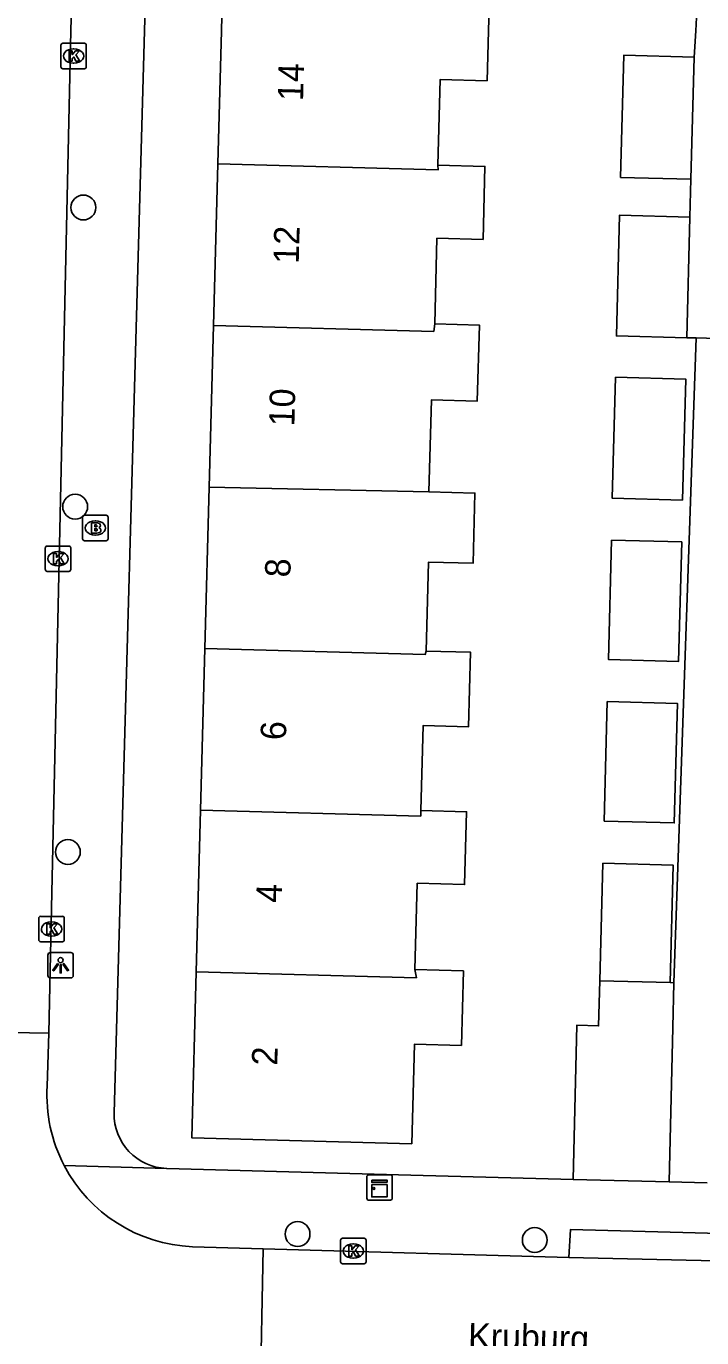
# Model space of a CAD drawing. Extents: x 162082 to 163393, y 388091 to 388632.
# Drawn here: x 162394.2 to 162420.8, y 388198.6 to 388250.2 of the extents above; entities that cross this region are included whole.
import ezdxf

# ---------------------------------------------------------------- set-up
doc = ezdxf.new("R2010")
doc.units = 0
for name, color, linetype in [('IMGEO_Boom', 7, 'Continuous'), ('IMGEO_Brandkraan', 7, 'Continuous'), ('IMGEO_Kast', 7, 'Continuous'), ('IMGEO_Kolk', 7, 'Continuous'), ('IMGEO_Lichtpunt', 7, 'Continuous'), ('IMGEO_Muur', 7, 'Continuous'), ('IMGEO_Openbare_ruimte_label', 7, 'Continuous'), ('IMGEO_Pand', 7, 'Continuous'), ('IMGEO_Pand_nummerreeks', 7, 'Continuous'), ('IMGEO_Rijbaan_lokaal_open', 7, 'Continuous'), ('IMGEO_Voetpad_open', 7, 'Continuous')]:
    doc.layers.add(name, color=color, linetype=linetype)

msp = doc.modelspace()

# ---------------------------------------------------------------- linework, layer by layer
at = {"layer": 'IMGEO_Boom'}
for centre in [(162396.454, 388243.049), (162396.132, 388231.285), (162395.845, 388217.705), (162404.875, 388202.681), (162414.202, 388202.447)]:
    msp.add_circle(centre, 0.489, dxfattribs=at)
at = {"layer": 'IMGEO_Brandkraan'}
for p, q in [((162396.426, 388230.021), (162396.426, 388230.873)), ((162396.501, 388230.947), (162397.353, 388230.947)), ((162396.914, 388230.727), (162396.939, 388230.727)), ((162397.427, 388230.873), (162397.427, 388230.021)), ((162396.937, 388230.167), (162396.912, 388230.167)), ((162397.353, 388229.947), (162396.501, 388229.947))]:
    msp.add_line(p, q, dxfattribs=at)
for points in [[(162396.426, 388230.021), (162396.426, 388230.873)], [(162396.501, 388230.947), (162397.353, 388230.947)], [(162397.427, 388230.873), (162397.427, 388230.021)], [(162396.774, 388230.647), (162396.774, 388230.247), (162396.987, 388230.247)], [(162397.005, 388230.647), (162396.774, 388230.647)], [(162396.953, 388230.566), (162396.899, 388230.566), (162396.899, 388230.49)], [(162396.899, 388230.49), (162396.952, 388230.49)], [(162396.961, 388230.414), (162396.899, 388230.414), (162396.899, 388230.333)], [(162396.899, 388230.333), (162396.961, 388230.333)], [(162397.353, 388229.947), (162396.501, 388229.947)]]:
    msp.add_lwpolyline(points, dxfattribs=at)
for centre, radius, start, end in [((162396.503, 388230.871), 0.0765, 91.552, 178.448), ((162396.503, 388230.871), 0.0765, 91.552, 178.448), ((162397.351, 388230.871), 0.0765, 1.552, 88.448), ((162397.351, 388230.871), 0.0765, 1.552, 88.448), ((162396.954, 388230.528), 0.0379, 267.8285, 90.9355), ((162396.962, 388230.373), 0.0404, 269.8759, 90.5077), ((162396.993, 388230.498), 0.251, 268.6676, 293.5347), ((162397.009, 388230.502), 0.145, 59.4692, 91.5367), ((162397.034, 388230.549), 0.0922, 285.5137, 58.1501), ((162397.039, 388230.357), 0.105, 301.3115, 78.989), ((162396.503, 388230.023), 0.0765, 181.552, 268.448), ((162396.503, 388230.023), 0.0765, 181.552, 268.448), ((162397.351, 388230.023), 0.0765, 271.552, 358.448), ((162397.351, 388230.023), 0.0765, 271.552, 358.448)]:
    msp.add_arc(centre, radius, start, end, dxfattribs=at)
for centre, major_axis, ratio, start_param, end_param in [((162396.913, 388230.447), (-0.387, 0.002), 0.722429, 4.712389, 7.853982), ((162396.938, 388230.447), (-0.39, 0.002), 0.717154, 1.570796, 4.712389)]:
    msp.add_ellipse(centre, major_axis=major_axis, ratio=ratio, start_param=start_param, end_param=end_param, dxfattribs=at)
at = {"layer": 'IMGEO_Kast'}
for p, q in [((162407.599, 388204.088), (162407.599, 388204.929)), ((162407.599, 388204.929), (162407.599, 388204.088)), ((162407.674, 388205.013), (162408.515, 388205.013)), ((162408.515, 388205.013), (162407.674, 388205.013)), ((162408.599, 388204.938), (162408.599, 388204.097)), ((162408.599, 388204.097), (162408.599, 388204.938)), ((162408.524, 388204.013), (162407.683, 388204.013)), ((162407.683, 388204.013), (162408.524, 388204.013))]:
    msp.add_line(p, q, dxfattribs=at)
for points in [[(162407.794, 388204.803), (162408.394, 388204.803), (162408.394, 388204.718), (162407.794, 388204.718), (162407.794, 388204.803)], [(162407.794, 388204.628), (162408.394, 388204.628), (162408.394, 388204.139), (162407.794, 388204.139), (162407.794, 388204.628)]]:
    msp.add_lwpolyline(points, dxfattribs=at)
msp.add_circle((162407.878, 388204.477), 0.0377, dxfattribs=at)
for centre, start, end in [((162407.677, 388204.935), 92.4484, 184.2845), ((162407.677, 388204.935), 92.4484, 184.2845), ((162408.521, 388204.935), 2.4484, 94.2845), ((162408.521, 388204.935), 2.4484, 94.2845), ((162407.677, 388204.091), 182.4484, 274.2845), ((162407.677, 388204.091), 182.4484, 274.2845), ((162408.521, 388204.091), 272.4484, 4.2845), ((162408.521, 388204.091), 272.4484, 4.2845)]:
    msp.add_arc(centre, 0.0779, start, end, dxfattribs=at)
at = {"layer": 'IMGEO_Kolk'}
for p, q in [((162395.569, 388248.579), (162395.569, 388249.431)), ((162395.644, 388249.505), (162396.496, 388249.505)), ((162396.057, 388249.285), (162396.082, 388249.285)), ((162396.57, 388249.431), (162396.57, 388248.579)), ((162396.08, 388248.725), (162396.055, 388248.725)), ((162396.496, 388248.505), (162395.644, 388248.505)), ((162394.959, 388228.811), (162394.959, 388229.663)), ((162395.034, 388229.737), (162395.886, 388229.737)), ((162395.96, 388229.663), (162395.96, 388228.811)), ((162395.447, 388229.517), (162395.472, 388229.517)), ((162395.886, 388228.737), (162395.034, 388228.737)), ((162395.47, 388228.957), (162395.445, 388228.957)), ((162394.702, 388214.249), (162394.702, 388215.101)), ((162394.777, 388215.175), (162395.629, 388215.175)), ((162395.19, 388214.955), (162395.215, 388214.955)), ((162395.703, 388215.101), (162395.703, 388214.249)), ((162395.629, 388214.175), (162394.777, 388214.175)), ((162395.213, 388214.395), (162395.188, 388214.395)), ((162406.566, 388201.589), (162406.566, 388202.441)), ((162406.641, 388202.515), (162407.493, 388202.515)), ((162407.054, 388202.295), (162407.079, 388202.295)), ((162407.567, 388202.441), (162407.567, 388201.589)), ((162407.493, 388201.515), (162406.641, 388201.515)), ((162407.077, 388201.735), (162407.052, 388201.735))]:
    msp.add_line(p, q, dxfattribs=at)
for points in [[(162395.569, 388248.579), (162395.569, 388249.431)], [(162395.644, 388249.505), (162396.496, 388249.505)], [(162396.57, 388249.431), (162396.57, 388248.579)], [(162395.89, 388249.205), (162396.013, 388249.205), (162396.013, 388249.054), (162396.143, 388249.205), (162396.307, 388249.205), (162396.161, 388249.054), (162396.314, 388248.805), (162396.162, 388248.805), (162396.077, 388248.969), (162396.013, 388248.902), (162396.013, 388248.805), (162395.89, 388248.805), (162395.89, 388249.205)], [(162396.496, 388248.505), (162395.644, 388248.505)], [(162394.959, 388228.811), (162394.959, 388229.663)], [(162395.034, 388229.737), (162395.886, 388229.737)], [(162395.96, 388229.663), (162395.96, 388228.811)], [(162395.28, 388229.437), (162395.403, 388229.437), (162395.403, 388229.286), (162395.533, 388229.437), (162395.697, 388229.437), (162395.551, 388229.286), (162395.704, 388229.037), (162395.552, 388229.037), (162395.467, 388229.201), (162395.403, 388229.134), (162395.403, 388229.037), (162395.28, 388229.037), (162395.28, 388229.437)], [(162395.886, 388228.737), (162395.034, 388228.737)], [(162394.702, 388214.249), (162394.702, 388215.101)], [(162394.777, 388215.175), (162395.629, 388215.175)], [(162395.023, 388214.875), (162395.146, 388214.875), (162395.146, 388214.724), (162395.276, 388214.875), (162395.44, 388214.875), (162395.294, 388214.724), (162395.447, 388214.475), (162395.295, 388214.475), (162395.21, 388214.639), (162395.146, 388214.572), (162395.146, 388214.475), (162395.023, 388214.475), (162395.023, 388214.875)], [(162395.703, 388215.101), (162395.703, 388214.249)], [(162395.629, 388214.175), (162394.777, 388214.175)], [(162406.566, 388201.589), (162406.566, 388202.441)], [(162406.641, 388202.515), (162407.493, 388202.515)], [(162407.567, 388202.441), (162407.567, 388201.589)], [(162406.887, 388202.215), (162407.01, 388202.215), (162407.01, 388202.064), (162407.14, 388202.215), (162407.304, 388202.215), (162407.158, 388202.064), (162407.311, 388201.815), (162407.159, 388201.815), (162407.074, 388201.979), (162407.01, 388201.912), (162407.01, 388201.815), (162406.887, 388201.815), (162406.887, 388202.215)], [(162407.493, 388201.515), (162406.641, 388201.515)]]:
    msp.add_lwpolyline(points, dxfattribs=at)
for centre, start, end in [((162395.646, 388249.429), 91.552, 178.448), ((162395.646, 388249.429), 91.552, 178.448), ((162396.494, 388249.429), 1.552, 88.448), ((162396.494, 388249.429), 1.552, 88.448), ((162395.646, 388248.581), 181.552, 268.448), ((162395.646, 388248.581), 181.552, 268.448), ((162396.494, 388248.581), 271.552, 358.448), ((162396.494, 388248.581), 271.552, 358.448), ((162395.036, 388229.661), 91.552, 178.448), ((162395.036, 388229.661), 91.552, 178.448), ((162395.884, 388229.661), 1.552, 88.448), ((162395.884, 388229.661), 1.552, 88.448), ((162395.036, 388228.813), 181.552, 268.448), ((162395.036, 388228.813), 181.552, 268.448), ((162395.884, 388228.813), 271.552, 358.448), ((162395.884, 388228.813), 271.552, 358.448), ((162394.779, 388215.099), 91.552, 178.448), ((162394.779, 388215.099), 91.552, 178.448), ((162395.627, 388215.099), 1.552, 88.448), ((162395.627, 388215.099), 1.552, 88.448), ((162394.779, 388214.251), 181.552, 268.448), ((162394.779, 388214.251), 181.552, 268.448), ((162395.627, 388214.251), 271.552, 358.448), ((162395.627, 388214.251), 271.552, 358.448), ((162406.643, 388202.439), 91.552, 178.448), ((162406.643, 388202.439), 91.552, 178.448), ((162407.491, 388202.439), 1.552, 88.448), ((162407.491, 388202.439), 1.552, 88.448), ((162406.643, 388201.591), 181.552, 268.448), ((162406.643, 388201.591), 181.552, 268.448), ((162407.491, 388201.591), 271.552, 358.448), ((162407.491, 388201.591), 271.552, 358.448)]:
    msp.add_arc(centre, 0.0765, start, end, dxfattribs=at)
for centre, major_axis, ratio, start_param, end_param in [((162396.056, 388249.005), (-0.387, 0.002), 0.722429, 4.712389, 7.853982), ((162396.081, 388249.005), (-0.39, 0.002), 0.717154, 1.570796, 4.712389), ((162395.446, 388229.237), (-0.387, 0.002), 0.722429, 4.712389, 7.853982), ((162395.471, 388229.237), (-0.39, 0.002), 0.717154, 1.570796, 4.712389), ((162395.189, 388214.675), (-0.387, 0.002), 0.722429, 4.712389, 7.853982), ((162395.214, 388214.675), (-0.39, 0.002), 0.717154, 1.570796, 4.712389), ((162407.053, 388202.015), (-0.387, 0.002), 0.722429, 4.712389, 7.853982), ((162407.078, 388202.015), (-0.39, 0.002), 0.717154, 1.570796, 4.712389)]:
    msp.add_ellipse(centre, major_axis=major_axis, ratio=ratio, start_param=start_param, end_param=end_param, dxfattribs=at)
at = {"layer": 'IMGEO_Lichtpunt'}
for p, q in [((162395.062, 388213.654), (162395.062, 388212.847)), ((162395.062, 388213.654), (162395.062, 388212.847)), ((162395.964, 388213.749), (162395.156, 388213.749)), ((162395.964, 388213.749), (162395.156, 388213.749)), ((162396.058, 388212.847), (162396.058, 388213.654)), ((162396.058, 388212.847), (162396.058, 388213.654)), ((162395.156, 388212.753), (162395.964, 388212.753)), ((162395.156, 388212.753), (162395.964, 388212.753))]:
    msp.add_line(p, q, dxfattribs=at)
for points in [[(162395.436, 388213.318), (162395.475, 388213.29), (162395.287, 388213.028), (162395.249, 388213.055), (162395.436, 388213.318)], [(162395.538, 388213.27), (162395.585, 388213.27), (162395.585, 388212.948), (162395.538, 388212.948), (162395.538, 388213.27)], [(162395.648, 388213.29), (162395.686, 388213.317), (162395.873, 388213.055), (162395.834, 388213.027), (162395.648, 388213.29)]]:
    msp.add_lwpolyline(points, dxfattribs=at)
msp.add_circle((162395.561, 388213.452), 0.0994, dxfattribs=at)
for centre, start, end in [((162395.156, 388213.654), 90, 180), ((162395.156, 388213.654), 90, 180), ((162395.964, 388213.654), 0, 90), ((162395.964, 388213.654), 0, 90), ((162395.156, 388212.847), 180, 270), ((162395.156, 388212.847), 180, 270), ((162395.964, 388212.847), 270, 0), ((162395.964, 388212.847), 270, 360)]:
    msp.add_arc(centre, 0.0946, start, end, dxfattribs=at)
at = {"layer": 'IMGEO_Muur'}
msp.add_lwpolyline([(162409.335, 388204.997), (162415.708, 388204.821)], dxfattribs=at)
at = {"layer": 'IMGEO_Pand'}
for points in [[(162401.914, 388251.116), (162401.884, 388250), (162401.744, 388244.762)], [(162410.387, 388244.713), (162410.477, 388248.082), (162412.328, 388248.032), (162412.38, 388250), (162412.404, 388250.901), (162410.524, 388250.951)], [(162420.47, 388248.96), (162417.702, 388249.034), (162417.574, 388244.235), (162420.342, 388244.161)], [(162420.47, 388248.96), (162420.342, 388244.161)], [(162401.744, 388244.762), (162401.574, 388238.408)], [(162401.744, 388244.762), (162410.398, 388244.53), (162410.387, 388244.713)], [(162410.267, 388238.471), (162410.357, 388241.839), (162412.166, 388241.791), (162412.243, 388244.663), (162410.387, 388244.713)], [(162420.173, 388237.927), (162417.412, 388238), (162417.538, 388242.749), (162420.3, 388242.675)], [(162420.3, 388242.675), (162420.173, 388237.927)], [(162401.404, 388232.055), (162401.574, 388238.408)], [(162401.574, 388238.408), (162410.227, 388238.176), (162410.267, 388238.471)], [(162410.267, 388238.471), (162412.023, 388238.424), (162411.943, 388235.436), (162410.137, 388235.484), (162410.041, 388231.871)], [(162420.01, 388231.54), (162420.137, 388236.301), (162417.376, 388236.375), (162417.249, 388231.613), (162420.01, 388231.54)], [(162401.404, 388232.055), (162401.234, 388225.701)], [(162410.041, 388231.871), (162401.404, 388232.055)], [(162409.934, 388225.608), (162410.027, 388229.107), (162411.777, 388229.06), (162411.851, 388231.822), (162410.041, 388231.871)], [(162417.22, 388229.972), (162419.982, 388229.899), (162419.857, 388225.202), (162417.096, 388225.276), (162417.22, 388229.972)], [(162401.234, 388225.701), (162401.064, 388219.347)], [(162409.934, 388225.608), (162409.886, 388225.469), (162401.234, 388225.701)], [(162409.72, 388219.337), (162409.809, 388222.676), (162411.598, 388222.628), (162411.677, 388225.562), (162409.934, 388225.608)], [(162416.926, 388218.922), (162419.687, 388218.848), (162419.812, 388223.545), (162417.05, 388223.618), (162416.926, 388218.922)], [(162400.895, 388212.993), (162401.064, 388219.347)], [(162401.064, 388219.347), (162409.716, 388219.115), (162409.72, 388219.337)], [(162409.72, 388219.337), (162411.52, 388219.288), (162411.443, 388216.425), (162409.579, 388216.475), (162409.488, 388213.082)], [(162416.757, 388212.642), (162416.879, 388217.264), (162419.641, 388217.191), (162419.518, 388212.569)], [(162400.895, 388212.993), (162400.72, 388206.464), (162409.368, 388206.233), (162409.472, 388210.148), (162411.315, 388210.098), (162411.394, 388213.032), (162409.488, 388213.082)], [(162409.488, 388213.082), (162409.545, 388212.761), (162400.895, 388212.993)], [(162416.757, 388212.642), (162416.71, 388210.869), (162415.854, 388210.89), (162415.708, 388204.821)], [(162419.518, 388212.569), (162416.757, 388212.642)], [(162419.484, 388204.73), (162419.63, 388210.799), (162419.672, 388212.565)], [(162419.672, 388212.565), (162419.518, 388212.569)], [(162419.484, 388204.73), (162415.708, 388204.821)]]:
    msp.add_lwpolyline(points, dxfattribs=at)
at = {"layer": 'IMGEO_Rijbaan_lokaal_open'}
for points in [[(162396.18, 388258.434), (162395.962, 388250), (162395.207, 388215.506), (162395.091, 388210.582)], [(162389.021, 388210.683), (162395.091, 388210.582)], [(162395.091, 388210.582), (162395.032, 388208.499)], [(162400.74, 388202.185), (162403.527, 388202.105)], [(162403.527, 388202.105), (162403.406, 388196.077)], [(162415.54, 388201.766), (162403.527, 388202.105)], [(162425.351, 388201.537), (162415.54, 388201.766)]]:
    msp.add_lwpolyline(points, dxfattribs=at)
for centre, radius, start, end in [((162400.974, 388208.141), 5.953, 176.5539, 207.6908), ((162400.983, 388208.141), 5.961, 207.6455, 267.6612)]:
    msp.add_arc(centre, radius, start, end, dxfattribs=at)
at = {"layer": 'IMGEO_Voetpad_open'}
for points in [[(162397.665, 388207.451), (162398.862, 388250), (162399.079, 388257.704), (162401.158, 388257.665)], [(162420.557, 388250.522), (162420.528, 388250), (162420.47, 388248.96)], [(162420.342, 388244.161), (162420.3, 388242.675)], [(162420.552, 388237.918), (162419.672, 388212.565)], [(162420.173, 388237.927), (162420.552, 388237.918)], [(162420.552, 388237.918), (162421.782, 388237.888)], [(162395.703, 388205.375), (162399.724, 388205.257), (162399.736, 388205.263)], [(162415.708, 388204.821), (162409.335, 388204.997), (162399.736, 388205.263)], [(162420.976, 388204.69), (162419.484, 388204.73)], [(162415.54, 388201.766), (162415.6, 388202.858), (162425.406, 388202.6), (162425.351, 388201.537)]]:
    msp.add_lwpolyline(points, dxfattribs=at)
msp.add_arc((162399.796, 388207.393), 2.131, 178.4534, 268.3994, dxfattribs=at)

# ---------------------------------------------------------------- texts
at = {"layer": 'IMGEO_Openbare_ruimte_label'}
msp.add_text('Kruburg', height=1, rotation=358.6252, dxfattribs=at).set_placement((162411.569, 388198.185))
at = {"layer": 'IMGEO_Pand_nummerreeks'}
for s, p in [('14', (162405.091, 388247.226)), ('12', (162404.92, 388240.825)), ('10', (162404.749, 388234.433)), ('8', (162404.59, 388228.497)), ('6', (162404.418, 388222.095)), ('4', (162404.247, 388215.697)), ('2', (162404.076, 388209.297))]:
    msp.add_text(s, height=1, rotation=88.469, dxfattribs=at).set_placement(p)

doc.saveas('drawing.dxf')
